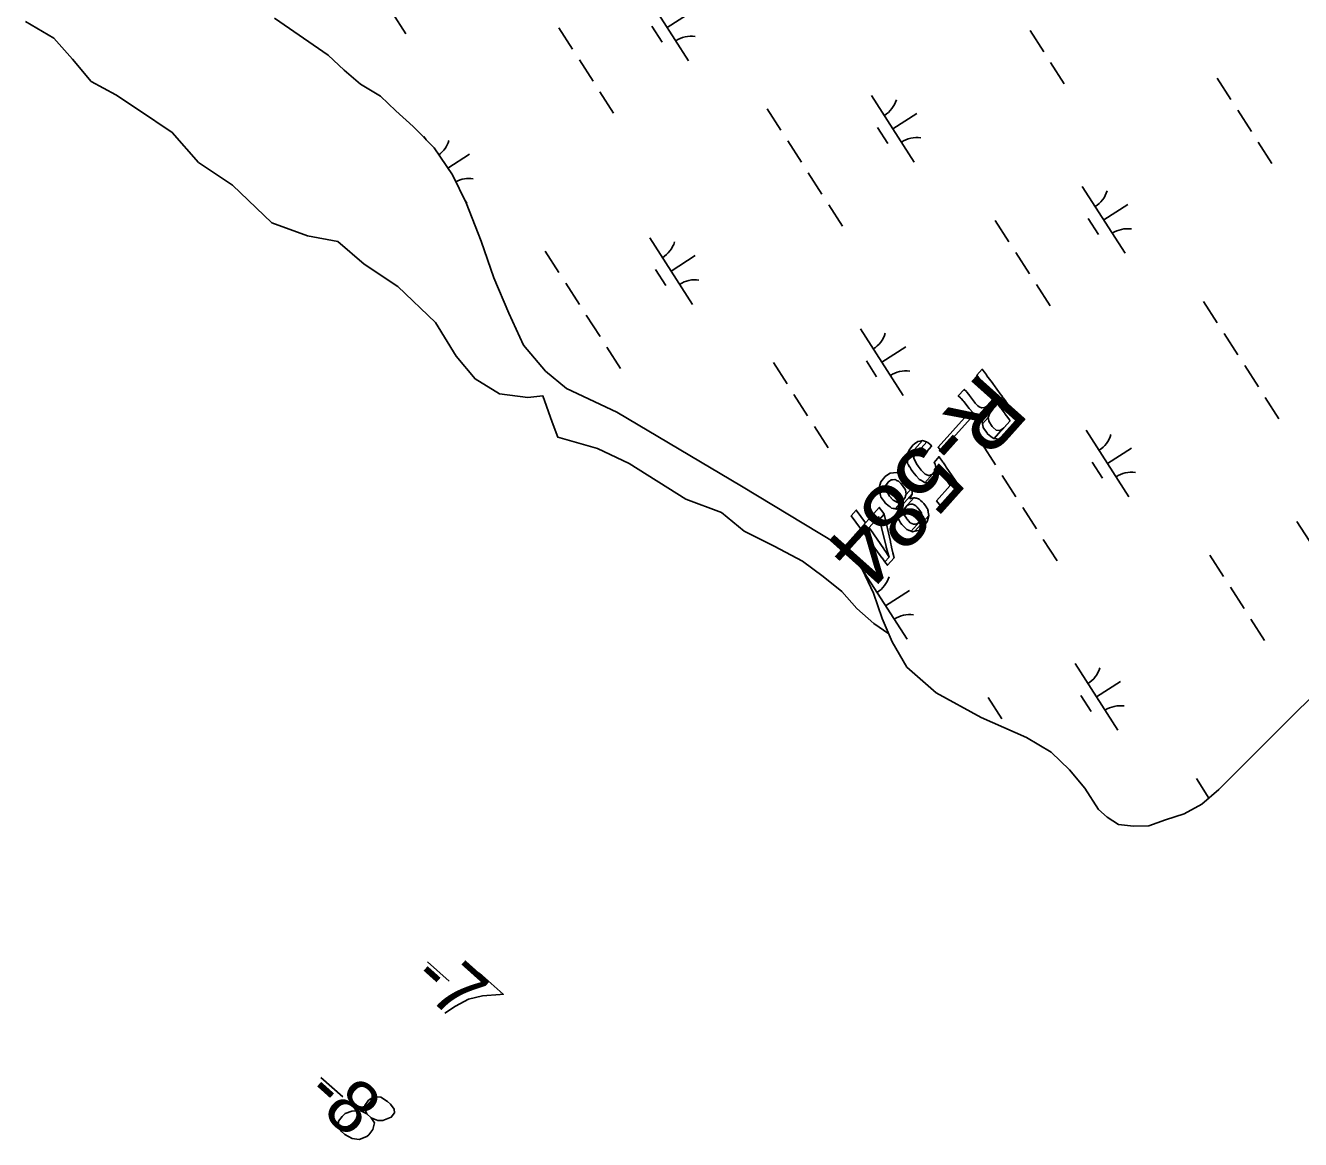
# Model space of a CAD drawing. Extents: x 3962991 to 3983549, y 181631 to 204078.
# Drawn here: x 3976588 to 3977393, y 191453 to 192156 of the extents above; entities that cross this region are included whole.
import ezdxf

# ---------------------------------------------------------------- set-up
doc = ezdxf.new("R2010")
doc.units = 0
for name, color, linetype in [('V-ANNO-MASK', 7, 'Continuous'), ('V-ANNO-MASK2', 7, 'Continuous'), ('V-RIVR-EDGE', 7, 'Continuous'), ('V-RIVR-RANG', 7, 'Continuous'), ('V-RIVR-RANG-IDEN', 7, 'Continuous'), ('V-WETL-SWMP', 7, 'Continuous')]:
    doc.layers.add(name, color=color, linetype=linetype)

msp = doc.modelspace()

# ---------------------------------------------------------------- linework, layer by layer
at = {"layer": 'V-ANNO-MASK2'}
for p, q in [((3976841.96, 191565.46), (3976855.71, 191553.13)), ((3976774.78, 191492.46), (3976788.53, 191480.13))]:
    msp.add_line(p, q, dxfattribs=at)
for points in [[(3977193.3, 191937.75), (3977192.12, 191939.37), (3977188.69, 191935.53), (3977189.88, 191933.92), (3977190.13, 191933.58), (3977191.34, 191931.93), (3977191.7, 191931.43), (3977194.89, 191927.07), (3977195.29, 191926.52), (3977196.78, 191924.49), (3977197.4, 191923.65), (3977198.38, 191922.31), (3977199.08, 191921.35), (3977199.31, 191921.05), (3977199.49, 191920.79), (3977190.11, 191910.29), (3977191.75, 191910.38), (3977194.36, 191911.83), (3977193.2, 191910), (3977192.1, 191906.9), (3977192.15, 191906.53), (3977201.92, 191917.47), (3977202.04, 191917.31), (3977202.67, 191916.45), (3977203.71, 191915.03), (3977204.05, 191914.57), (3977206.13, 191911.73), (3977206.67, 191910.99), (3977208.23, 191908.87), (3977209.36, 191907.33), (3977209.59, 191907), (3977209.6, 191907.01), (3977209.69, 191906.87), (3977209.74, 191906.81), (3977199.65, 191895.53), (3977203.28, 191895.3), (3977206.61, 191897.15), (3977209.7, 191900.35), (3977215.74, 191907.11), (3977215.63, 191907.25), (3977214.89, 191908.28), (3977213.16, 191910.64), (3977213.12, 191910.7), (3977213.01, 191910.83), (3977212.78, 191911.15), (3977211.65, 191912.7), (3977210.1, 191914.82), (3977209.55, 191915.56), (3977207.47, 191918.4), (3977207.14, 191918.86), (3977206.1, 191920.28), (3977205.47, 191921.15), (3977205.35, 191921.3), (3977205.18, 191921.54), (3977204.43, 191922.57), (3977204.21, 191922.86), (3977203.62, 191923.67), (3977202.92, 191924.62), (3977202.73, 191924.88), (3977202.51, 191925.18), (3977201.81, 191926.15), (3977200.82, 191927.48), (3977200.21, 191928.32), (3977198.72, 191930.36), (3977198.32, 191930.91), (3977195.13, 191935.26), (3977194.77, 191935.76), (3977193.55, 191937.41)], [(3977182.11, 191925.23), (3977180.75, 191926.65), (3977177.01, 191922.46), (3977178.51, 191921.19), (3977178.79, 191920.89), (3977180.16, 191919.43), (3977180.54, 191918.94), (3977183.79, 191914.65), (3977184.2, 191914.11), (3977185.91, 191912.32), (3977186.61, 191911.58), (3977188.08, 191910.79), (3977189.15, 191910.23), (3977189.67, 191910.26), (3977190.11, 191910.29), (3977196.26, 191917.17), (3977194.24, 191915.38), (3977193.65, 191915.27), (3977191.76, 191914.91), (3977190.27, 191915.67), (3977189.32, 191916.15), (3977187.68, 191918), (3977187.23, 191918.5), (3977184.04, 191922.86), (3977183.66, 191923.34), (3977182.39, 191924.92)], [(3977184.72, 191908.28), (3977182.82, 191910.87), (3977164.29, 191890.13), (3977166.19, 191887.54)], [(3977196.98, 191911.65), (3977199.12, 191914.32), (3977192.15, 191906.53), (3977192.19, 191906.29), (3977192.39, 191904.95), (3977195.93, 191908.91)], [(3977196.33, 191906.78), (3977195.93, 191908.91), (3977192.39, 191904.95), (3977192.71, 191902.73), (3977193.03, 191902.25), (3977195.03, 191899.32), (3977195.55, 191898.54), (3977197.57, 191896.95), (3977199.05, 191895.79), (3977199.35, 191895.55), (3977199.56, 191895.53), (3977205.21, 191901.85), (3977204.66, 191901.48), (3977203.34, 191900.6), (3977201.02, 191900.81), (3977199.09, 191902.5), (3977198.41, 191903.1), (3977196.46, 191906.09)], [(3977206.97, 191903.71), (3977205.2, 191901.85), (3977199.56, 191895.53), (3977199.65, 191895.53)], [(3977149.39, 191892.17), (3977148.41, 191891.43), (3977145.93, 191888.3), (3977145.45, 191887.02), (3977144.49, 191884.5), (3977144.63, 191883.28), (3977154.52, 191894.35), (3977153, 191894.02), (3977151.4, 191893.68)], [(3977155.79, 191893.95), (3977154.52, 191894.34), (3977144.63, 191883.28), (3977144.81, 191881.67), (3977150.53, 191888.07), (3977152.24, 191889.28), (3977152.56, 191889.51), (3977153.55, 191889.5), (3977153.55, 191889.5), (3977153.67, 191889.5), (3977157.24, 191893.49), (3977157.14, 191893.52), (3977156.37, 191893.76), (3977156.27, 191893.79)], [(3977157.68, 191893.14), (3977157.23, 191893.49), (3977153.67, 191889.5), (3977154.41, 191889.48), (3977154.58, 191889.38), (3977155.96, 191888.52), (3977156.02, 191888.47), (3977157.12, 191887.35), (3977160.21, 191890.8), (3977159.18, 191892), (3977159.12, 191892.05), (3977157.84, 191893.03)], [(3977149.1, 191885.76), (3977150.53, 191888.07), (3977144.81, 191881.67), (3977144.88, 191881.05), (3977144.9, 191880.93), (3977145.01, 191879.94), (3977145.05, 191879.86), (3977145.36, 191879.36), (3977145.46, 191879.19), (3977146.33, 191877.74), (3977146.37, 191877.68), (3977147.38, 191876.01), (3977148.29, 191874.5), (3977150.35, 191872.15), (3977152.25, 191869.99), (3977152.38, 191869.84), (3977152.92, 191869.53), (3977153.35, 191869.28), (3977154.77, 191868.44), (3977155.06, 191868.27), (3977155.81, 191867.83), (3977155.81, 191867.84), (3977155.97, 191867.74), (3977160.73, 191873.06), (3977160.34, 191872.91), (3977158.63, 191872.25), (3977158.28, 191872.38), (3977156.64, 191872.96), (3977156.14, 191873.13), (3977155.7, 191873.55), (3977155.56, 191873.69), (3977153.5, 191875.67), (3977151.63, 191878.24), (3977150.61, 191879.62), (3977149.73, 191881.44), (3977149.7, 191881.51), (3977148.94, 191883.07), (3977148.95, 191883.38), (3977149.01, 191884.29), (3977149.02, 191884.43), (3977149.09, 191885.63)], [(3977165.04, 191884), (3977164.92, 191884.17), (3977161.71, 191880.57), (3977161.81, 191880.38), (3977162.13, 191879.83), (3977162.38, 191879.37), (3977162.76, 191877.38), (3977162.61, 191876.71), (3977162.61, 191876.71), (3977162.24, 191875.03), (3977160.73, 191873.06), (3977155.98, 191867.74), (3977156.27, 191867.56), (3977157.4, 191867.6), (3977165.05, 191876.16), (3977165.83, 191875.03), (3977166.13, 191874.59), (3977166.35, 191874.25), (3977171.98, 191866), (3977163.34, 191856.33), (3977165.75, 191853.05), (3977177.32, 191865.99), (3977175.01, 191869.39), (3977169.38, 191877.64), (3977169.15, 191877.97), (3977168.85, 191878.41), (3977168.08, 191879.54), (3977167.61, 191880.24), (3977167.41, 191880.53), (3977167.3, 191880.69), (3977166.81, 191881.41), (3977166.61, 191881.7), (3977165.68, 191883.06), (3977165.39, 191883.48)], [(3977164.97, 191874.07), (3977165.05, 191876.16), (3977157.4, 191867.6), (3977159.25, 191867.67), (3977159.96, 191867.69), (3977161.33, 191868.64), (3977162.61, 191869.52), (3977162.61, 191869.52), (3977164.33, 191871.99), (3977164.61, 191872.89)], [(3977131.71, 191872.26), (3977130.77, 191871.64), (3977128.17, 191868.29), (3977127.75, 191866.77), (3977126.9, 191863.69), (3977127.34, 191861.99), (3977133.08, 191868.42), (3977133.58, 191868.75), (3977133.63, 191868.78), (3977134.7, 191869.49), (3977135.57, 191869.59), (3977136.91, 191869.75), (3977137.58, 191869.44), (3977138.04, 191869.22), (3977139.25, 191868.65), (3977139.32, 191868.61), (3977140.69, 191867.2), (3977141.81, 191866.04), (3977141.84, 191866), (3977142.62, 191864.78), (3977142.77, 191864.52), (3977143.61, 191863.19), (3977143.86, 191861.85), (3977143.89, 191861.7), (3977144.1, 191860.57), (3977143.99, 191860.16), (3977147.9, 191864.54), (3977147.81, 191864.72), (3977147.37, 191865.58), (3977147.31, 191865.7), (3977146.78, 191866.74), (3977146.05, 191868.19), (3977145.91, 191868.46), (3977144.95, 191869.48), (3977144.91, 191869.52), (3977143.8, 191870.69), (3977142.46, 191872.13), (3977142.4, 191872.18), (3977141.21, 191872.77), (3977140.75, 191873), (3977140.1, 191873.32), (3977139.27, 191873.73), (3977138.73, 191874), (3977138.42, 191874.14), (3977138.41, 191874.15), (3977138.19, 191874.13), (3977136.07, 191873.95), (3977134, 191873.77)], [(3977131.99, 191866.97), (3977133.08, 191868.42), (3977127.34, 191861.99), (3977127.38, 191861.81), (3977127.39, 191861.82), (3977127.39, 191861.8), (3977131.9, 191866.85)], [(3977131.69, 191866.12), (3977131.9, 191866.85), (3977127.39, 191861.8), (3977127.49, 191861.42), (3977127.49, 191861.42), (3977127.66, 191860.75), (3977127.93, 191859.71), (3977128.14, 191858.89), (3977128.44, 191858.48), (3977129.2, 191857.41), (3977129.25, 191857.35), (3977130.42, 191855.71), (3977130.42, 191855.72), (3977131.38, 191854.37), (3977131.42, 191854.34), (3977132.53, 191853.49), (3977132.76, 191853.32), (3977132.76, 191853.32), (3977133.96, 191852.4), (3977134.82, 191851.74), (3977134.92, 191851.66), (3977135.98, 191851.48), (3977136.19, 191851.44), (3977136.61, 191851.36), (3977137.14, 191851.27), (3977137.3, 191851.24), (3977142.08, 191856.59), (3977141.69, 191856.36), (3977140.4, 191855.6), (3977139.9, 191855.58), (3977139.63, 191855.57), (3977138.38, 191855.52), (3977138.2, 191855.51), (3977137.23, 191856.05), (3977135.87, 191856.8), (3977135.68, 191857.01), (3977134.74, 191858.06), (3977134.7, 191858.1), (3977133.61, 191859.29), (3977132.55, 191861.04), (3977132.51, 191861.11), (3977131.81, 191862.25), (3977131.69, 191862.86), (3977131.52, 191863.72), (3977131.3, 191864.82)], [(3977147.91, 191864), (3977147.9, 191864.54), (3977143.99, 191860.16), (3977143.75, 191859.35), (3977143.46, 191858.34), (3977142.08, 191856.59), (3977137.3, 191851.25), (3977138.03, 191851.11), (3977139.91, 191851.67), (3977147.97, 191860.69), (3977147.94, 191862.2), (3977147.92, 191863.13), (3977147.92, 191863.33)], [(3977147.53, 191859.75), (3977147.96, 191860.68), (3977139.91, 191851.67), (3977140.45, 191851.83), (3977139.28, 191849.46), (3977138.97, 191848.82), (3977139.03, 191847.23), (3977148.89, 191858.26), (3977146.86, 191857.66), (3977146.52, 191857.56)], [(3977129.38, 191849.09), (3977127.14, 191852.14), (3977112.08, 191835.29), (3977114.32, 191832.24), (3977126.87, 191846.27), (3977127.3, 191844.54), (3977130.28, 191847.88)], [(3977149.08, 191858.22), (3977148.88, 191858.26), (3977139.03, 191847.23), (3977139.04, 191846.98), (3977144.42, 191853), (3977144.85, 191853.29), (3977145.99, 191854.06), (3977146.83, 191854.14), (3977147.28, 191854.18), (3977147.29, 191854.19), (3977148.09, 191854.26), (3977148.67, 191853.94), (3977149.06, 191853.72), (3977149.07, 191853.73), (3977150.18, 191853.1), (3977151.06, 191852.22), (3977151.34, 191851.93), (3977152.11, 191851.17), (3977152.17, 191851.1), (3977153.13, 191849.63), (3977153.74, 191848.69), (3977153.75, 191848.64), (3977154.05, 191847.35), (3977154.05, 191847.36), (3977154.17, 191846.83), (3977154.25, 191846.48), (3977153.91, 191845.16), (3977153.91, 191845.16), (3977153.76, 191844.6), (3977152.52, 191842.95), (3977147.32, 191837.13), (3977148.08, 191836.83), (3977149.69, 191837.16), (3977158.43, 191846.93), (3977158.22, 191848.17), (3977158.06, 191849.14), (3977158.02, 191849.37), (3977157.96, 191849.7), (3977157.83, 191850.49), (3977157.77, 191850.86), (3977157.52, 191851.24), (3977156.9, 191852.17), (3977156.88, 191852.2), (3977156.26, 191853.13), (3977155.29, 191854.6), (3977155.24, 191854.67), (3977154.43, 191855.39), (3977154.12, 191855.65), (3977153.19, 191856.47), (3977152.26, 191857.29), (3977151.92, 191857.58), (3977151.21, 191857.74), (3977150.59, 191857.88), (3977150.24, 191857.96), (3977149.6, 191858.1), (3977149.22, 191858.18)], [(3977143.21, 191851.46), (3977144.42, 191853), (3977139.04, 191846.98), (3977139.04, 191846.8), (3977139.06, 191846.31), (3977139.09, 191845.49), (3977142.58, 191849.39), (3977142.98, 191850.69)], [(3977118.45, 191842.42), (3977112.6, 191850.41), (3977109.43, 191846.86), (3977115.27, 191838.86)], [(3977134.17, 191830.59), (3977130.27, 191847.87), (3977127.3, 191844.54), (3977131.45, 191827.54), (3977131.55, 191827.09), (3977132.32, 191824.27), (3977132.36, 191824.13), (3977133.37, 191820.75), (3977130.72, 191817.79), (3977132.29, 191815.64), (3977136.47, 191820.32), (3977135.77, 191823.44), (3977134.96, 191827.04), (3977134.93, 191827.19), (3977134.27, 191830.13)], [(3977142.66, 191849.02), (3977142.58, 191849.39), (3977139.09, 191845.49), (3977139.11, 191845.04), (3977139.41, 191844.54), (3977139.75, 191843.96), (3977139.99, 191843.57), (3977140.65, 191842.45), (3977141.32, 191841.32), (3977141.61, 191841.04), (3977142.38, 191840.29), (3977142.45, 191840.23), (3977143.66, 191839.04), (3977144.44, 191838.29), (3977144.46, 191838.26), (3977145.54, 191837.84), (3977145.98, 191837.66), (3977146.26, 191837.55), (3977146.89, 191837.31), (3977147.15, 191837.2), (3977147.32, 191837.13), (3977152.52, 191842.95), (3977151.86, 191842.47), (3977150.87, 191841.76), (3977149.92, 191841.64), (3977149.48, 191841.58), (3977148.81, 191841.49), (3977147.8, 191841.98), (3977147.76, 191842), (3977146.75, 191842.49), (3977145.58, 191843.73), (3977145.52, 191843.79), (3977144.77, 191844.58), (3977144.54, 191844.93), (3977143.83, 191846), (3977143.11, 191847.06), (3977142.99, 191847.59), (3977142.82, 191848.36)], [(3977157.54, 191843.81), (3977158.42, 191846.93), (3977149.69, 191837.16), (3977152.03, 191837.64), (3977153.33, 191838.7), (3977157.38, 191843.23)], [(3977155.06, 191840.11), (3977157.38, 191843.23), (3977153.33, 191838.7)], [(3977121.54, 191838.11), (3977120.68, 191839.35), (3977117.52, 191835.81), (3977118.41, 191834.6), (3977127.12, 191822.7), (3977127.35, 191822.39), (3977128.83, 191820.37), (3977128.91, 191820.27), (3977130.72, 191817.79), (3977133.37, 191820.75), (3977131.71, 191823.41), (3977131.65, 191823.52), (3977130.24, 191825.63), (3977130.02, 191825.95)]]:
    msp.add_lwpolyline(points, close=True, dxfattribs=at)
for points in [[(3976874.66, 191558.47), (3976889.79, 191544.91), (3976887.93, 191544.81), (3976876.77, 191543.83), (3976867.91, 191541.85), (3976859.75, 191537.48), (3976852.89, 191532.99)], [(3976803.69, 191469.38), (3976806.44, 191466.92), (3976807.41, 191466.41), (3976810.64, 191465.28), (3976813.82, 191465.27), (3976819.13, 191467.24), (3976821.22, 191469.97), (3976820.9, 191472.38), (3976818.68, 191475.43), (3976816.72, 191477.19), (3976812.46, 191479.95), (3976809.83, 191480.18), (3976806.89, 191479.27), (3976804.71, 191478.03), (3976802.47, 191474.73), (3976802.2, 191472.85), (3976803.69, 191469.38), (3976799.85, 191471.41), (3976794.26, 191471.11), (3976790.05, 191469.57), (3976788.09, 191467.78), (3976785.82, 191464.85), (3976785.83, 191461.3), (3976787.48, 191458.41), (3976789.84, 191456.29), (3976794.45, 191453.93), (3976798.79, 191453.23), (3976803.72, 191455.19), (3976804.98, 191456.19), (3976807.6, 191459.51), (3976808.49, 191463.67), (3976806.44, 191466.92)]]:
    msp.add_lwpolyline(points, dxfattribs=at)
at = {"layer": 'V-RIVR-EDGE'}
msp.add_lwpolyline([(3976588.29, 192158.85), (3976606.1, 192148.17), (3976617.97, 192135.11), (3976629.84, 192120.86), (3976645.28, 192112.55), (3976659.53, 192103.05), (3976680.9, 192088.8), (3976697.52, 192069.81), (3976718.89, 192055.56), (3976743.82, 192031.82), (3976766.37, 192023.51), (3976785.37, 192019.95), (3976801.99, 192005.7), (3976823.36, 191991.45), (3976847.1, 191968.9), (3976860.16, 191947.53), (3976872.04, 191933.28), (3976887.47, 191923.78), (3976905.28, 191921.41), (3976914.78, 191922.59), (3976920.71, 191905.97), (3976924.27, 191896.48), (3976949.21, 191889.35), (3976969.39, 191879.86), (3977005, 191857.3), (3977027.56, 191848.99), (3977041.81, 191837.12), (3977060.8, 191827.62), (3977078.61, 191818.12), (3977091.67, 191808.62), (3977103.54, 191799.12), (3977113.04, 191788.44), (3977123.73, 191778.94), (3977133.15, 191772.29)], dxfattribs=at)
at = {"layer": 'V-WETL-SWMP'}
for p, q in [((3976979.82, 192176.09), (3977006.8, 192134)), ((3976819.77, 192164.55), (3976828.41, 192151.08)), ((3976993.31, 192155.05), (3977008.46, 192164.76)), ((3976924.91, 192154.8), (3976933.55, 192141.33)), ((3976983.58, 192155.93), (3976990.05, 192145.83)), ((3977222.33, 192153.03), (3977230.96, 192139.56)), ((3976937.87, 192134.59), (3976946.5, 192121.12)), ((3977235.28, 192132.83), (3977243.91, 192119.36)), ((3977340.42, 192123.08), (3977349.05, 192109.61)), ((3976950.82, 192114.39), (3976959.45, 192100.92)), ((3977122.27, 192112.14), (3977149.25, 192070.05)), ((3977056.39, 192103.67), (3977065.02, 192090.2)), ((3977135.76, 192091.1), (3977150.91, 192100.81)), ((3977353.37, 192102.87), (3977362.01, 192089.4)), ((3976839.79, 192086.32), (3976841.19, 192084.13)), ((3977126.03, 192091.98), (3977132.5, 192081.88)), ((3977069.34, 192083.46), (3977077.98, 192069.99)), ((3977366.32, 192082.67), (3977374.96, 192069.2)), ((3976854.9, 192066.31), (3976868.43, 192074.99)), ((3977082.29, 192063.26), (3977090.93, 192049.79)), ((3977255.29, 192054.6), (3977282.28, 192012.51)), ((3976865.7, 192045.91), (3976866.77, 192044.23)), ((3977095.25, 192043.05), (3977103.88, 192029.58)), ((3977268.78, 192033.55), (3977283.94, 192043.27)), ((3977200.39, 192033.3), (3977209.02, 192019.83)), ((3977259.05, 192034.44), (3977265.53, 192024.34)), ((3976982.24, 192022.37), (3977009.22, 191980.28)), ((3976916.36, 192013.89), (3976924.99, 192000.42)), ((3977213.34, 192013.1), (3977221.98, 191999.63)), ((3976995.73, 192001.32), (3977010.88, 192011.04)), ((3976986, 192002.21), (3976992.47, 191992.11)), ((3976929.31, 191993.69), (3976937.94, 191980.22)), ((3977226.29, 191992.89), (3977234.93, 191979.42)), ((3977331.86, 191982.17), (3977340.5, 191968.7)), ((3976942.26, 191973.48), (3976950.9, 191960.02)), ((3977115.26, 191964.83), (3977142.25, 191922.73)), ((3977344.81, 191961.97), (3977353.45, 191948.5)), ((3976955.21, 191953.28), (3976963.85, 191939.81)), ((3977128.75, 191943.78), (3977143.91, 191953.49)), ((3977060.36, 191943.53), (3977068.99, 191930.06)), ((3977119.02, 191944.67), (3977125.5, 191934.56)), ((3977357.77, 191941.77), (3977366.4, 191928.3)), ((3977073.31, 191923.33), (3977081.94, 191909.86)), ((3977370.72, 191921.56), (3977379.35, 191908.09)), ((3977086.26, 191903.12), (3977094.9, 191889.65)), ((3977257.71, 191900.88), (3977284.69, 191858.78)), ((3977191.83, 191892.4), (3977200.46, 191878.93)), ((3977271.2, 191879.83), (3977286.36, 191889.54)), ((3977261.47, 191880.72), (3977267.95, 191870.61)), ((3977204.78, 191872.2), (3977213.42, 191858.73)), ((3977217.73, 191851.99), (3977226.37, 191838.52)), ((3977390.73, 191843.33), (3977417.72, 191801.24)), ((3977230.69, 191831.79), (3977239.32, 191818.32)), ((3977335.83, 191822.04), (3977344.46, 191808.57)), ((3977117.68, 191811.1), (3977144.66, 191769.01)), ((3977131.17, 191790.06), (3977146.32, 191799.77)), ((3977348.78, 191801.83), (3977357.42, 191788.36)), ((3977361.73, 191781.63), (3977370.37, 191768.16)), ((3977250.7, 191753.56), (3977277.69, 191711.47)), ((3977264.19, 191732.51), (3977279.35, 191742.23)), ((3977195.8, 191732.26), (3977204.43, 191718.79)), ((3977254.46, 191733.4), (3977260.94, 191723.3)), ((3977208.75, 191712.06), (3977208.87, 191711.88)), ((3977327.27, 191681.13), (3977335.23, 191668.71))]:
    msp.add_line(p, q, dxfattribs=at)
for points in [[(3977191.37, 191719.52), (3977163.16, 191735.08), (3977144.45, 191751.39), (3977135.26, 191767.28), (3977129.05, 191782.03), (3977123.42, 191797.98), (3977116.63, 191812.72), (3977110.54, 191820.94), (3977099.69, 191829.66), (3977040.21, 191865.47), (3976961.52, 191912.24), (3976929.76, 191927.13), (3976916.49, 191938.19), (3976902.53, 191954.59), (3976893.26, 191974.64), (3976883.95, 191997.06), (3976875.82, 192020.1), (3976866.48, 192044.31), (3976857.84, 192061.99), (3976846.25, 192079.02), (3976832.94, 192092.46), (3976822.06, 192102.37), (3976812.4, 192111.61), (3976799.77, 192119.23), (3976789.52, 192128.07), (3976779.25, 192137.5), (3976745.54, 192161)], [(3977413.24, 191744.82), (3977392.19, 191724.83), (3977341.37, 191674.01), (3977330.83, 191664.91), (3977319.64, 191658.77), (3977307.82, 191655), (3977297.19, 191651.24), (3977287.68, 191651.08), (3977278.15, 191652.1), (3977270.94, 191656.73), (3977265.51, 191661.39), (3977256.95, 191674.91), (3977247.23, 191686.62), (3977235.74, 191697.72), (3977220.13, 191706.95), (3977191.37, 191719.52)]]:
    msp.add_lwpolyline(points, dxfattribs=at)
for centre, start, end in [((3977008.42, 192131.92), 81.89186, 123.43552), ((3977121.05, 192114.48), 301.89187, 343.43553), ((3977150.87, 192067.97), 81.89186, 123.43552), ((3976838.57, 192088.65), 307.26113, 343.43553), ((3976868.39, 192042.15), 81.89186, 118.52501), ((3977254.08, 192056.93), 301.89187, 343.43553), ((3977283.89, 192010.43), 81.89186, 123.43552), ((3976981.02, 192024.7), 301.89187, 343.43553), ((3977010.84, 191978.2), 81.89186, 123.43552), ((3977114.05, 191967.16), 301.89187, 343.43553), ((3977143.86, 191920.65), 81.89186, 123.43552), ((3977256.49, 191903.21), 301.89187, 343.43553), ((3977286.31, 191856.7), 81.89186, 123.43552), ((3977116.46, 191813.44), 301.89187, 343.43553), ((3977146.28, 191766.93), 81.89186, 123.43552), ((3977249.49, 191755.89), 301.89187, 343.43553), ((3977279.3, 191709.39), 81.89186, 123.43552)]:
    msp.add_arc(centre, 17.62, start, end, dxfattribs=at)

# ---------------------------------------------------------------- texts
at = {"layer": 'V-ANNO-MASK'}
for s, height, rotation, p in [('R-584  ', 41.5, 228.20792, (3977191.7, 191938.9)), ('-7', 33.5, 318.13308, (3976830.7, 191552.89)), ('-8', 33.5, 318.13308, (3976763.52, 191479.88))]:
    msp.add_text(s, height=height, rotation=rotation, dxfattribs=at).set_placement(p)
at = {"layer": 'V-RIVR-RANG'}
for s, p in [('-7', (3976830.7, 191552.89)), ('-8', (3976763.52, 191479.88))]:
    msp.add_text(s, height=33.5, rotation=318.13308, dxfattribs=at).set_placement(p)
at = {"layer": 'V-RIVR-RANG-IDEN'}
msp.add_text('R-584  ', height=41.5, rotation=228.20792, dxfattribs=at).set_placement((3977191.7, 191938.9))

doc.saveas('drawing.dxf')
